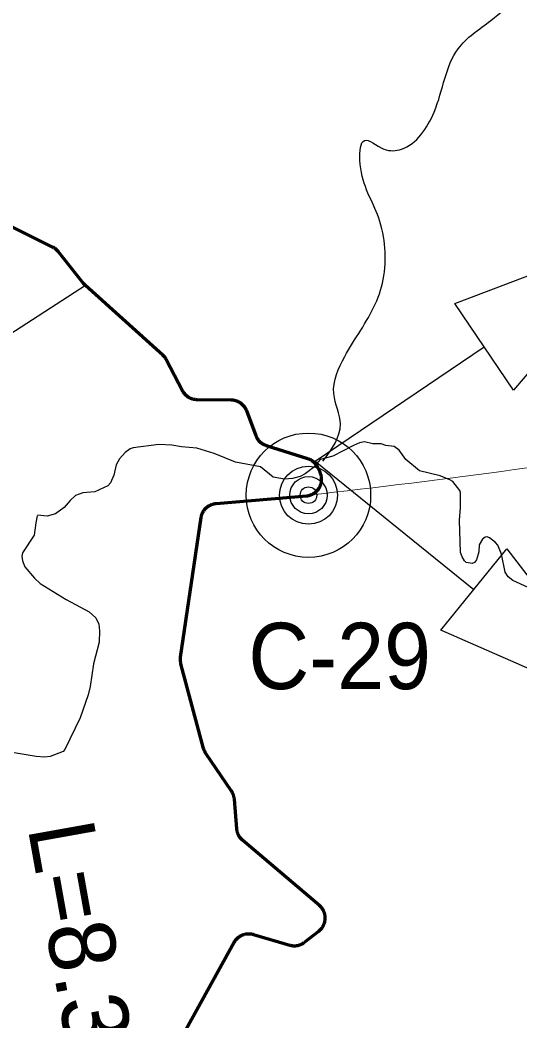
# Model space of a CAD drawing. Extents: x -1643653 to 4543381, y 1624270 to 13878484.
# Drawn here: x 740638 to 743654, y 8948296 to 8954334 of the extents above; entities that cross this region are included whole.
import ezdxf

# ---------------------------------------------------------------- set-up
doc = ezdxf.new("R2010")
doc.units = 0
doc.header["$LTSCALE"] = 160
for name, color, linetype, lineweight in [('15', 7, 'Continuous', 25), ('24', 7, 'Continuous', 25), ('50', 7, 'Continuous', 13), ('54', 7, 'Continuous', 25), ('60', 7, 'Continuous', 13), ('61', 7, 'Continuous', 70)]:
    doc.layers.add(name, color=color, linetype=linetype, lineweight=lineweight)

msp = doc.modelspace()

# ---------------------------------------------------------------- linework, layer by layer
at = {"layer": '15'}
for radius in [375, 175, 112.5, 50]:
    msp.add_circle((742378.1, 8951467.9), radius, dxfattribs=at)
at = {"layer": '24'}
for points in [[(743290.9, 8951495.2), (743248.2, 8951550.2), (743231.5, 8951561), (743171.6, 8951584.4), (743048.4, 8951615.2), (742965.9, 8951683.7), (742925.7, 8951738.8), (742894.4, 8951760.8), (742845.4, 8951768.3), (742815.9, 8951778.6), (742766, 8951777.7), (742716.6, 8951788.8), (742685.1, 8951783.5), (742648.7, 8951768.3), (742524.2, 8951702.7), (742447.7, 8951683), (742407.6, 8951634.3), (742357.9, 8951596.9), (742328.7, 8951581.1), (742280.7, 8951568.7), (742234, 8951565.1), (742165, 8951577.1), (742087.8, 8951638.7), (741938.6, 8951667.3), (741808.5, 8951720.2), (741704.5, 8951751), (741611.1, 8951758.6), (741553.7, 8951769.6), (741475.3, 8951774.6), (741320.3, 8951752.9), (741303.4, 8951747.1), (741273, 8951726.1), (741237.6, 8951687.6), (741218.7, 8951651.1), (741204.4, 8951588), (741183, 8951543), (741167.8, 8951524.4)], [(741167.8, 8951524.4), (741089.3, 8951489), (741089.3, 8951489), (741016, 8951482.8), (740973, 8951465.6), (740940.3, 8951435.8), (740904, 8951394.2), (740853, 8951356.3), (740802.3, 8951342.2), (740743.8, 8951348.2)], [(743703.7, 8950911.4), (743611.1, 8950952.8), (743583.1, 8950975.6), (743564.7, 8951003.7), (743541.9, 8951111.5), (743520.7, 8951166.1), (743507, 8951183.2), (743470.1, 8951211.5), (743455.2, 8951217.2), (743444.2, 8951215.6), (743428.2, 8951203.4), (743408.1, 8951169.4), (743406.6, 8951126.7), (743392.1, 8951078), (743379.9, 8951062.8), (743364.8, 8951055.6), (743329.4, 8951061.5), (743319.3, 8951071), (743304.7, 8951095.8), (743295.6, 8951122), (743288.9, 8951318.1), (743294.6, 8951394.4), (743294.6, 8951481.4), (743290.9, 8951495.2)], [(740740.6, 8951344), (740732.7, 8951300.9), (740723.5, 8951227.5), (740653.5, 8951120.8), (740649.5, 8951099.8), (740653.7, 8951072.3), (740666.3, 8951035.6), (740724.8, 8950967.6), (740759, 8950935.8), (740915.7, 8950837.9), (741054.4, 8950764.3), (741094.9, 8950728.4), (741114.1, 8950689.2), (741117.5, 8950649.2), (741115.4, 8950581.4), (741081.2, 8950451.3), (741060.2, 8950314.6), (741048.6, 8950264.3), (741001.4, 8950124.1), (740907.9, 8949933.5), (740897.7, 8949920.9), (740820.4, 8949892.3), (740784.7, 8949888.2), (740735.3, 8949891.9), (740602.9, 8949913.7)]]:
    msp.add_lwpolyline(points, dxfattribs=at)
msp.add_spline([(742465, 8951672.5), (742570.2, 8951896.3), (742530.8, 8952080.7), (742596.6, 8952304.5), (742780.8, 8952620.5), (742833.4, 8952791.7), (742793.9, 8953160.4), (742688.7, 8953489.6), (742715, 8953608.1), (742833.4, 8953555.4), (742938.7, 8953555.4), (743136.1, 8953779.2), (743280.8, 8954161.1), (743478.2, 8954332.2), (743780.8, 8954635.1), (744030.8, 8955095.9), (744188.8, 8955556.8), (744215.1, 8955938.6), (744123, 8956320.5), (743886.1, 8956926.2)], degree=3, dxfattribs=at)
at = {"layer": '50'}
msp.add_spline([(742378.1, 8951467.9), (744857.3, 8951843.2), (747806.2, 8952478.7), (753658.5, 8951389.2), (756788.8, 8951389.2)], degree=3, dxfattribs=at)
at = {"layer": '54'}
for p, q in [((741033, 8952733.3), (739999.3, 8952064.6)), ((742418.5, 8951672.5), (743437.3, 8952363.5)), ((742418.5, 8951672.5), (743375.6, 8950898.3))]:
    msp.add_line(p, q, dxfattribs=at)
for points in [[(743260.1, 8952624.8), (744443.7, 8953072.9), (743614.6, 8952102.2)], [(743574.2, 8951143.8), (744346.8, 8950141.5), (743177.1, 8950652.8)]]:
    msp.add_lwpolyline(points, close=True, dxfattribs=at)
at = {"layer": '60', "lineweight": 25}
msp.add_spline([(814781, 9009175.5), (814787.2, 9009173.4), (814796.9, 9009173.4), (814799.4, 9009172.4), (814805.1, 9009174.5), (814805.6, 9009176.5), (814811.7, 9009179.5), (814811.7, 9009179.5), (814801.5, 9009181), (814790.7, 9009181.5), (814784.1, 9009183.1), (814777.4, 9009185.1), (814778.4, 9009175.5)], degree=3, dxfattribs=at)
at = {"layer": '61'}
for points in [[(740862.1, 8952944.3), (740860.1, 8952946.3), (740858.1, 8952948.3), (740856, 8952950.2), (740853.9, 8952952.1), (740851.7, 8952953.8), (740849.4, 8952955.6), (740847.1, 8952957.2), (740844.8, 8952958.8), (740842.4, 8952960.4), (740840, 8952961.8), (740837.5, 8952963.2), (740835, 8952964.5), (740834.3, 8952964.9), (739766.2, 8953499.3)], [(741995.1, 8951996.3), (741993.5, 8951998.7), (741991.8, 8952001), (741990.1, 8952003.2), (741988.3, 8952005.4), (741986.5, 8952007.5), (741984.6, 8952009.6), (741982.6, 8952011.7), (741980.6, 8952013.6), (741978.5, 8952015.6), (741976.4, 8952017.4), (741974.2, 8952019.2), (741971.9, 8952020.9), (741969.7, 8952022.6), (741967.3, 8952024.2), (741965, 8952025.8), (741962.6, 8952027.2), (741960.1, 8952028.6), (741957.6, 8952030), (741955.1, 8952031.2), (741952.5, 8952032.4), (741949.9, 8952033.5), (741947.3, 8952034.6), (741944.6, 8952035.6), (741941.9, 8952036.4), (741939.2, 8952037.3), (741936.5, 8952038), (741933.8, 8952038.7), (741931, 8952039.2), (741928.2, 8952039.8), (741925.4, 8952040.2), (741922.6, 8952040.5), (741919.8, 8952040.8), (741917, 8952041), (741914.1, 8952041.1), (741913, 8952041.1), (741705.8, 8952043.7), (741703, 8952043.8), (741700.2, 8952044), (741697.4, 8952044.2), (741694.5, 8952044.5), (741691.7, 8952044.9), (741689, 8952045.4), (741686.2, 8952045.9), (741683.4, 8952046.6), (741680.7, 8952047.3), (741678, 8952048.1), (741675.3, 8952048.9), (741672.6, 8952049.9), (741670, 8952050.9), (741667.3, 8952052), (741664.8, 8952053.1), (741662.2, 8952054.4), (741659.7, 8952055.7), (741657.2, 8952057), (741654.8, 8952058.5), (741652.4, 8952060), (741650.1, 8952061.6), (741647.8, 8952063.2), (741645.5, 8952064.9), (741643.3, 8952066.7), (741641.2, 8952068.5), (741639.1, 8952070.4), (741637, 8952072.4), (741635, 8952074.4), (741633.1, 8952076.5), (741631.2, 8952078.6), (741629.4, 8952080.8), (741627.7, 8952083), (741626, 8952085.2), (741624.4, 8952087.6), (741622.8, 8952089.9), (741621.3, 8952092.3), (741619.9, 8952094.8), (741618.6, 8952097.3), (741618.4, 8952097.5), (741520.3, 8952285.4), (741519, 8952287.9), (741517.6, 8952290.4), (741516.1, 8952292.8), (741514.6, 8952295.1), (741512.9, 8952297.5), (741511.3, 8952299.7), (741509.5, 8952302), (741507.7, 8952304.1), (741505.8, 8952306.3), (741503.9, 8952308.3), (741501.9, 8952310.3), (741499.9, 8952312.3), (741498.7, 8952313.4), (741033, 8952733.3), (741030.9, 8952735.2), (741028.9, 8952737.2), (741026.9, 8952739.2), (741025, 8952741.3), (741023.2, 8952743.5), (741021.8, 8952745.1), (740867.7, 8952937.9), (740865.9, 8952940.1), (740864, 8952942.2), (740862.1, 8952944.3)], [(742453.6, 8951536.8), (742454.4, 8951539.5), (742455, 8951542.3), (742455.6, 8951545.1), (742456, 8951547.8), (742456.4, 8951550.6), (742456.8, 8951553.5), (742457, 8951556.3), (742457.2, 8951559.1), (742457.3, 8951561.9), (742457.3, 8951564.8), (742457.2, 8951567.6), (742457, 8951570.4), (742456.8, 8951573.2), (742456.5, 8951576), (742456.1, 8951578.8), (742455.6, 8951581.6), (742455.1, 8951584.4), (742454.4, 8951587.2), (742453.7, 8951589.9), (742452.9, 8951592.6), (742452.1, 8951595.3), (742451.1, 8951598), (742450.1, 8951600.6), (742449, 8951603.2), (742447.9, 8951605.8), (742447.8, 8951605.9), (742434.1, 8951635.1), (742432.9, 8951637.6), (742431.6, 8951640.1), (742430.2, 8951642.6), (742428.8, 8951645), (742427.2, 8951647.4), (742425.7, 8951649.8), (742424, 8951652.1), (742422.3, 8951654.3), (742420.5, 8951656.5), (742418.7, 8951658.7), (742416.8, 8951660.7), (742414.8, 8951662.8), (742412.8, 8951664.8), (742410.8, 8951666.7), (742408.6, 8951668.6), (742406.5, 8951670.4), (742404.2, 8951672.1), (742402, 8951673.8), (742399.6, 8951675.4), (742397.3, 8951677), (742394.9, 8951678.5), (742392.4, 8951679.9), (742389.9, 8951681.2), (742387.4, 8951682.5), (742384.8, 8951683.7), (742382.2, 8951684.8), (742379.6, 8951685.9), (742377, 8951686.9), (742374.3, 8951687.8), (742373.5, 8951688), (742125.3, 8951765.8), (742122.6, 8951766.7), (742120, 8951767.7), (742117.3, 8951768.7), (742114.7, 8951769.8), (742112.2, 8951771), (742109.6, 8951772.2), (742107.1, 8951773.6), (742104.7, 8951775), (742102.2, 8951776.4), (742099.9, 8951778), (742097.5, 8951779.6), (742095.2, 8951781.2), (742093, 8951783), (742090.8, 8951784.7), (742088.7, 8951786.6), (742086.6, 8951788.5), (742084.6, 8951790.5), (742082.6, 8951792.5), (742080.7, 8951794.6), (742078.8, 8951796.7), (742077, 8951798.9), (742075.3, 8951801.1), (742073.6, 8951803.4), (742072, 8951805.8), (742070.5, 8951808.1), (742069, 8951810.6), (742067.6, 8951813), (742066.3, 8951815.5), (742065, 8951818), (742063.8, 8951820.6), (742062.7, 8951823.2), (742061.7, 8951825.8), (742061.6, 8951826.2), (742005.3, 8951976.2), (742004.3, 8951978.8), (742003.2, 8951981.5), (742002, 8951984), (742000.8, 8951986.6), (741999.5, 8951989.1), (741998.1, 8951991.5), (741996.6, 8951994), (741995.1, 8951996.3)], [(741605.7, 8950472.9), (741605.6, 8950475.7), (741605.6, 8950478.6), (741605.7, 8950481.4), (741605.9, 8950484.2), (741606.2, 8950487), (741606.5, 8950489.8), (741606.7, 8950491), (741730.4, 8951332.6), (741730.9, 8951335.4), (741731.4, 8951338.2), (741732, 8951340.9), (741732.7, 8951343.7), (741733.5, 8951346.4), (741734.3, 8951349.1), (741735.2, 8951351.8), (741736.2, 8951354.4), (741737.3, 8951357), (741738.4, 8951359.6), (741739.6, 8951362.2), (741740.9, 8951364.7), (741742.3, 8951367.2), (741743.7, 8951369.6), (741745.2, 8951372), (741746.8, 8951374.4), (741748.4, 8951376.7), (741750.1, 8951379), (741751.8, 8951381.2), (741753.7, 8951383.3), (741755.5, 8951385.5), (741757.5, 8951387.5), (741759.5, 8951389.5), (741761.5, 8951391.5), (741763.6, 8951393.4), (741765.8, 8951395.2), (741768, 8951397), (741770.2, 8951398.7), (741772.5, 8951400.3), (741774.9, 8951401.9), (741777.3, 8951403.4), (741779.7, 8951404.8), (741782.2, 8951406.2), (741784.7, 8951407.5), (741787.2, 8951408.7), (741789.8, 8951409.9), (741792.5, 8951411), (741795.1, 8951412), (741797.8, 8951412.9), (741800.5, 8951413.8), (741803.2, 8951414.5), (741805.9, 8951415.2), (741808.7, 8951415.9), (741811.5, 8951416.4), (741814.2, 8951416.9), (741817, 8951417.3), (741819.8, 8951417.6), (741820.9, 8951417.7), (742365.7, 8951463.8), (742368.5, 8951464.1), (742371.3, 8951464.5), (742374.1, 8951464.9), (742376.9, 8951465.4), (742379.7, 8951466), (742382.4, 8951466.7), (742385.1, 8951467.4), (742387.8, 8951468.3), (742390.5, 8951469.2), (742393.2, 8951470.1), (742395.8, 8951471.2), (742398.4, 8951472.3), (742401, 8951473.5), (742403.5, 8951474.8), (742406, 8951476.1), (742408.4, 8951477.6), (742410.8, 8951479), (742413.2, 8951480.6), (742415.5, 8951482.2), (742417.8, 8951483.9), (742420, 8951485.6), (742422.2, 8951487.4), (742424.3, 8951489.3), (742426.4, 8951491.2), (742428.4, 8951493.2), (742430.4, 8951495.2), (742432.3, 8951497.3), (742434.1, 8951499.5), (742435.9, 8951501.7), (742437.6, 8951503.9), (742439.3, 8951506.2), (742440.8, 8951508.6), (742442.4, 8951511), (742443.8, 8951513.4), (742445.2, 8951515.8), (742446.5, 8951518.3), (742447.8, 8951520.9), (742448.9, 8951523.5), (742450, 8951526.1), (742451, 8951528.7), (742452, 8951531.4), (742452.8, 8951534.1), (742453.6, 8951536.8)], [(742478.8, 8948922.9), (742478.6, 8948925.7), (742478.3, 8948928.5), (742478, 8948931.3), (742477.5, 8948934.1), (742477, 8948936.9), (742476.4, 8948939.7), (742475.8, 8948942.4), (742475, 8948945.1), (742474.2, 8948947.8), (742473.3, 8948950.5), (742472.3, 8948953.2), (742471.3, 8948955.8), (742470.1, 8948958.4), (742468.9, 8948961), (742467.7, 8948963.5), (742466.3, 8948966), (742464.9, 8948968.4), (742463.5, 8948970.8), (742461.9, 8948973.2), (742460.3, 8948975.5), (742458.6, 8948977.8), (742456.9, 8948980), (742455.1, 8948982.2), (742453.2, 8948984.3), (742451.3, 8948986.4), (742449.3, 8948988.4), (742447.3, 8948990.4), (742445.2, 8948992.3), (742443.6, 8948993.6), (741980.5, 8949386.8), (741978.3, 8949388.6), (741976.3, 8949390.6), (741974.2, 8949392.5), (741972.3, 8949394.6), (741970.4, 8949396.7), (741968.5, 8949398.8), (741966.7, 8949401), (741965, 8949403.2), (741963.3, 8949405.5), (741961.8, 8949407.9), (741960.2, 8949410.2), (741958.8, 8949412.7), (741957.4, 8949415.1), (741956.1, 8949417.6), (741954.8, 8949420.2), (741953.6, 8949422.8), (741952.5, 8949425.4), (741951.5, 8949428), (741950.6, 8949430.7), (741949.7, 8949433.3), (741948.9, 8949436.1), (741948.2, 8949438.8), (741947.5, 8949441.5), (741946.9, 8949444.3), (741946.5, 8949447.1), (741946, 8949449.9), (741945.7, 8949452.7), (741945.5, 8949454.8), (741930.8, 8949634.9), (741930.5, 8949637.7), (741930.1, 8949640.5), (741929.7, 8949643.3), (741929.2, 8949646.1), (741928.6, 8949648.9), (741928, 8949651.6), (741927.2, 8949654.4), (741926.4, 8949657.1), (741925.5, 8949659.8), (741924.5, 8949662.4), (741923.5, 8949665), (741922.4, 8949667.6), (741921.2, 8949670.2), (741919.9, 8949672.7), (741918.6, 8949675.2), (741917.2, 8949677.7), (741915.7, 8949680.1), (741914.1, 8949682.5), (741913.7, 8949683.1), (741759.8, 8949909), (741758.2, 8949911.3), (741756.8, 8949913.7), (741755.3, 8949916.2), (741754, 8949918.7), (741752.7, 8949921.2), (741751.5, 8949923.7), (741750.3, 8949926.3), (741749.3, 8949928.9), (741748.3, 8949931.6), (741747.4, 8949934.3), (741746.5, 8949937), (741745.8, 8949939.4), (741609, 8950450.6), (741608.3, 8950453.3), (741607.7, 8950456.1), (741607.2, 8950458.9), (741606.7, 8950461.7), (741606.3, 8950464.5), (741606, 8950467.3), (741605.8, 8950470.1), (741605.7, 8950472.9)], [(741965.1, 8948807.5), (741967.5, 8948809), (741969.9, 8948810.4), (741972.5, 8948811.7), (741975, 8948813), (741977.6, 8948814.1), (741980.2, 8948815.2), (741982.8, 8948816.3), (741985.5, 8948817.2), (741988.2, 8948818.1), (741990.9, 8948818.9), (741993.6, 8948819.6), (741996.3, 8948820.3), (741999.1, 8948820.8), (742001.9, 8948821.3), (742004.7, 8948821.7), (742007.5, 8948822.1), (742010.3, 8948822.3), (742013.2, 8948822.5), (742016, 8948822.6), (742018.8, 8948822.6), (742021.6, 8948822.5), (742024.5, 8948822.4), (742027.3, 8948822.2), (742030.1, 8948821.8), (742032.9, 8948821.5), (742035.7, 8948821), (742038.5, 8948820.5), (742041.2, 8948819.8), (742044, 8948819.1), (742046.1, 8948818.5), (742264.7, 8948754.2), (742267.4, 8948753.4), (742270.2, 8948752.7), (742272.9, 8948752.1), (742275.7, 8948751.6), (742278.5, 8948751.2), (742281.3, 8948750.8), (742284.1, 8948750.5), (742286.9, 8948750.3), (742289.8, 8948750.2), (742292.6, 8948750.1), (742295.4, 8948750.1), (742298.2, 8948750.3), (742301.1, 8948750.5), (742303.9, 8948750.7), (742306.7, 8948751.1), (742309.5, 8948751.5), (742312.3, 8948752), (742315, 8948752.6), (742317.8, 8948753.2), (742320.5, 8948754), (742323.2, 8948754.8), (742325.9, 8948755.7), (742328.6, 8948756.7), (742331.2, 8948757.7), (742333.8, 8948758.8), (742336.3, 8948760), (742338.9, 8948761.3), (742341.4, 8948762.6), (742343.8, 8948764), (742346.2, 8948765.5), (742348.6, 8948767.1), (742350.9, 8948768.7), (742353.2, 8948770.3), (742354.6, 8948771.3), (742440.6, 8948838.6), (742442.8, 8948840.4), (742444.9, 8948842.2), (742447, 8948844.1), (742449, 8948846.1), (742451, 8948848.1), (742453, 8948850.2), (742454.8, 8948852.3), (742456.6, 8948854.5), (742458.4, 8948856.7), (742460.1, 8948859), (742461.7, 8948861.3), (742463.2, 8948863.6), (742464.7, 8948866), (742466.2, 8948868.5), (742467.5, 8948871), (742468.8, 8948873.5), (742470, 8948876.1), (742471.1, 8948878.7), (742472.2, 8948881.3), (742473.2, 8948883.9), (742474.1, 8948886.6), (742474.9, 8948889.3), (742475.7, 8948892), (742476.3, 8948894.8), (742476.9, 8948897.5), (742477.5, 8948900.3), (742477.9, 8948903.1), (742478.3, 8948905.9), (742478.6, 8948908.7), (742478.8, 8948911.6), (742478.9, 8948914.4), (742478.9, 8948917.2), (742478.9, 8948920), (742478.8, 8948922.9)], [(741414.1, 8947839.1), (741930.3, 8948771.1), (741931.8, 8948773.5), (741933.2, 8948775.9), (741934.8, 8948778.3), (741936.4, 8948780.6), (741938.1, 8948782.9), (741939.8, 8948785.1), (741941.6, 8948787.3), (741943.5, 8948789.4), (741945.4, 8948791.5), (741947.3, 8948793.5), (741949.4, 8948795.5), (741951.5, 8948797.4), (741953.6, 8948799.3), (741955.8, 8948801), (741958.1, 8948802.8), (741960.3, 8948804.4), (741962.7, 8948806), (741965.1, 8948807.5)]]:
    msp.add_lwpolyline(points, dxfattribs=at)

# ---------------------------------------------------------------- texts
at = {"layer": '15', "width": 0.95}
msp.add_text('C-29', height=400, dxfattribs=at).set_placement((742015.3, 8950298.2))
at = {"layer": '50'}
msp.add_text('L=8.396 m', height=400, rotation=280.171, dxfattribs=at).set_placement((740683.5, 8949462.7))

doc.saveas('drawing.dxf')
